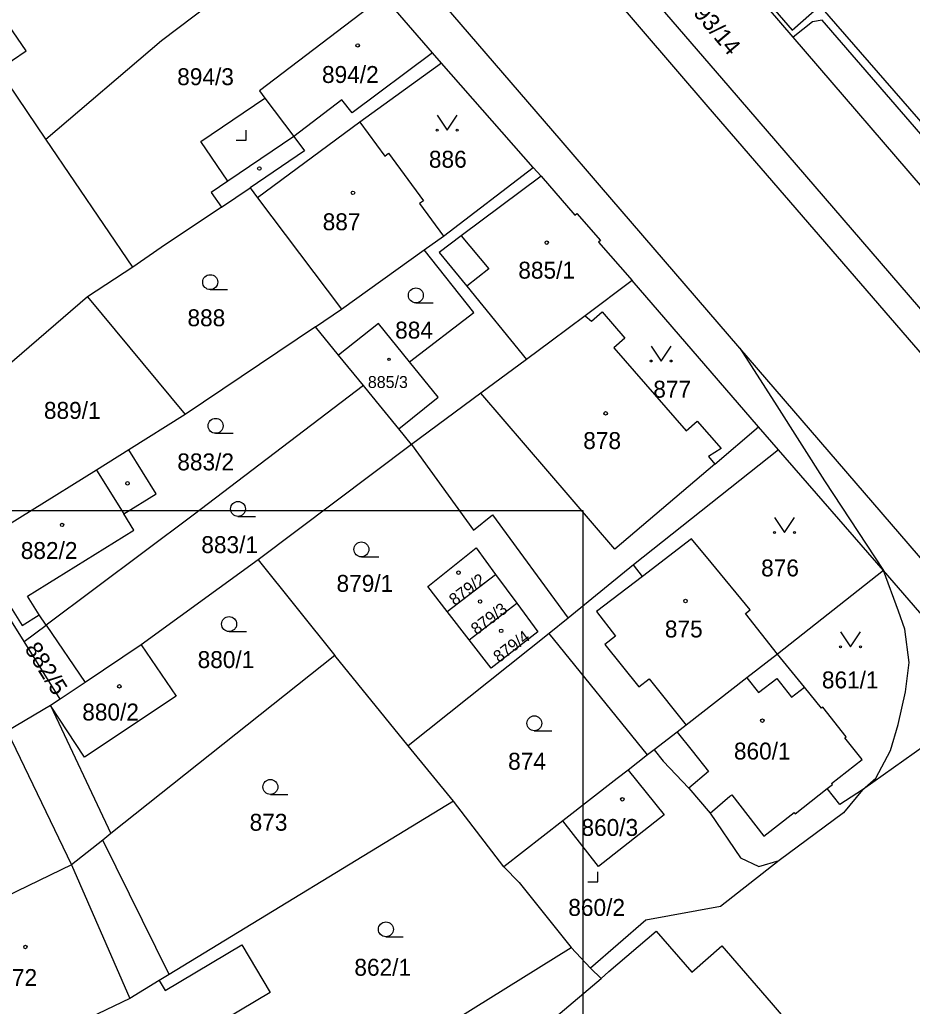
# Model space of a CAD drawing. Extents: x -496682 to -495776, y -1088797 to -1088018.
# Drawn here: x -496193.9 to -496104.3, y -1088214 to -1088115 of the extents above; entities that cross this region are included whole.
import ezdxf

# ---------------------------------------------------------------- set-up
doc = ezdxf.new("R2010")
doc.units = 0
for name, color, linetype in [('Hranice parcel', 7, 'Continuous'), ('Parcelní čísla', 7, 'Continuous'), ('Vnitřní kresba', 7, 'Continuous'), ('Vrstva 63', 7, 'Continuous'), ('Značky budov', 7, 'Continuous'), ('Značky kultur', 7, 'Continuous')]:
    doc.layers.add(name, color=color, linetype=linetype)

msp = doc.modelspace()

# ---------------------------------------------------------------- linework, layer by layer
at = {"layer": 'Hranice parcel'}
for p, q in [((-496152.45, -1088118.29), (-496157.35, -1088112.6)), ((-496075.55, -1088164.09), (-496116.26, -1088116.72)), ((-496151.53, -1088119.31), (-496152.45, -1088118.29)), ((-496142.34, -1088129.81), (-496151.53, -1088119.31)), ((-496182.51, -1088139.79), (-496191.24, -1088126.97)), ((-496151.33, -1088136.69), (-496142.34, -1088129.81)), ((-496153.28, -1088138.08), (-496151.33, -1088136.69)), ((-496161.59, -1088144.03), (-496153.28, -1088138.08)), ((-496182.51, -1088139.79), (-496187.08, -1088142.78)), ((-496132.39, -1088141.15), (-496137.12, -1088144.68)), ((-496119.71, -1088155.84), (-496132.39, -1088141.15)), ((-496187.08, -1088142.78), (-496198.32, -1088152.5)), ((-496187.08, -1088142.78), (-496177.27, -1088154.6)), ((-496164.19, -1088145.79), (-496161.59, -1088144.03)), ((-496164.19, -1088145.79), (-496177.27, -1088154.6)), ((-496161.87, -1088148.63), (-496164.19, -1088145.79)), ((-496159.38, -1088151.68), (-496161.87, -1088148.63)), ((-496177.27, -1088154.6), (-496182.92, -1088158.15)), ((-496154.55, -1088157.61), (-496155.82, -1088156.05)), ((-496117.71, -1088158.15), (-496119.71, -1088155.84)), ((-496154.55, -1088157.61), (-496169.94, -1088169.21)), ((-496117.71, -1088158.15), (-496132.27, -1088169.7)), ((-496107.18, -1088170.28), (-496117.71, -1088158.15)), ((-496169.94, -1088169.21), (-496181.67, -1088177.72)), ((-496169.94, -1088169.21), (-496162.24, -1088178.79)), ((-496107.18, -1088170.28), (-496117.81, -1088178.66)), ((-496096.21, -1088183.01), (-496107.18, -1088170.28)), ((-496150.97, -1088174.38), (-496146.11, -1088170.67)), ((-496146.11, -1088170.67), (-496143.99, -1088173.55)), ((-496148.77, -1088177.22), (-496150.97, -1088174.38)), ((-496148.77, -1088177.22), (-496143.99, -1088173.55)), ((-496138.84, -1088175.04), (-496140.75, -1088176.58)), ((-496193.41, -1088177.4), (-496191.21, -1088175.76)), ((-496191.21, -1088175.76), (-496187.29, -1088181.5)), ((-496189.82, -1088183.19), (-496193.41, -1088177.4)), ((-496140.75, -1088176.58), (-496154.9, -1088187.88)), ((-496130.86, -1088188.79), (-496140.75, -1088176.58)), ((-496181.67, -1088177.72), (-496187.29, -1088181.5)), ((-496162.24, -1088178.79), (-496184.73, -1088196.69)), ((-496154.9, -1088187.88), (-496162.24, -1088178.79)), ((-496187.29, -1088181.5), (-496189.82, -1088183.19)), ((-496189.82, -1088183.19), (-496190.77, -1088183.83)), ((-496096.21, -1088183.01), (-496109.3, -1088192.3)), ((-496190.77, -1088183.83), (-496195.13, -1088186.39)), ((-496190.77, -1088183.83), (-496184.73, -1088196.69)), ((-496150.33, -1088193.43), (-496154.9, -1088187.88)), ((-496130.21, -1088188.26), (-496130.86, -1088188.79)), ((-496130.86, -1088188.79), (-496132.79, -1088190.31)), ((-496150.33, -1088193.43), (-496178.87, -1088210.84)), ((-496145.28, -1088200.01), (-496150.33, -1088193.43)), ((-496139.35, -1088195.4), (-496145.28, -1088200.01)), ((-496184.73, -1088196.69), (-496185.54, -1088197.33)), ((-496178.87, -1088210.84), (-496185.54, -1088197.33)), ((-496162.6, -1088223.08), (-496138.52, -1088208.12)), ((-496138.52, -1088208.12), (-496136.58, -1088210.21)), ((-496178.87, -1088210.84), (-496179.86, -1088211.45)), ((-496136.58, -1088210.21), (-496135.52, -1088211.22))]:
    msp.add_line(p, q, dxfattribs=at)
for points in [[(-496121.59, -1088147.94), (-496135.68, -1088131.58), (-496139.54, -1088127.1), (-496152.9, -1088111.52), (-496154.28, -1088109.93), (-496192.25, -1088065.81), (-496197.08, -1088060.92), (-496210.28, -1088048.82), (-496224.09, -1088036.2), (-496238.46, -1088023.17), (-496242.493, -1088019.486)], [(-496181.151, -1088019.486), (-496180.97, -1088024.95), (-496179.9, -1088035.45), (-496177.55, -1088046.36), (-496174.16, -1088056.24), (-496169.6, -1088065.68), (-496164.16, -1088074.78), (-496158.66, -1088082.86), (-496152.68, -1088090.79), (-496145.28, -1088099.81), (-496124.8, -1088123.7), (-496085.88, -1088168.81)], [(-496116.26, -1088116.72), (-496137.09, -1088092.45), (-496144.2, -1088083.68), (-496150.73, -1088075.21), (-496154.49, -1088069.71), (-496160.82, -1088074.53), (-496156.15, -1088081.34), (-496150.43, -1088088.98), (-496143.13, -1088097.97), (-496122.6, -1088121.81), (-496081, -1088170.14)], [(-496129.35, -1088100.96), (-496116.34, -1088116.02), (-496113.57, -1088113.57)], [(-496191.24, -1088126.97), (-496179.64, -1088117.06), (-496163.37, -1088104.73)], [(-496157.35, -1088112.6), (-496169.82, -1088122.1), (-496169.28, -1088122.83), (-496166.37, -1088126.68)], [(-496113.57, -1088113.57), (-496085.45, -1088145.89), (-496086.2, -1088146.36)], [(-496191.24, -1088126.97), (-496196, -1088119.97), (-496193.23, -1088118.07), (-496195.38, -1088114.92)], [(-496086.2, -1088146.36), (-496113.33, -1088115), (-496114.3, -1088115.18), (-496116.26, -1088116.72)], [(-496152.45, -1088118.29), (-496160.5, -1088124.31), (-496161.54, -1088123.01), (-496166.37, -1088126.68)], [(-496151.53, -1088119.31), (-496159.75, -1088125.24), (-496157.24, -1088128.65), (-496156.86, -1088128.37), (-496153.36, -1088133.14), (-496153.74, -1088133.42), (-496151.33, -1088136.69)], [(-496166.37, -1088126.68), (-496172.98, -1088131.17), (-496174.67, -1088132.32), (-496173.63, -1088133.79)], [(-496142.34, -1088129.81), (-496141.55, -1088130.68), (-496138.15, -1088134.58), (-496137.97, -1088134.42), (-496135.59, -1088137.14), (-496135.77, -1088137.3), (-496132.39, -1088141.15)], [(-496173.63, -1088133.79), (-496170.75, -1088131.83), (-496169.99, -1088132.84), (-496161.59, -1088144.03)], [(-496173.63, -1088133.79), (-496179.66, -1088137.84), (-496182.51, -1088139.79)], [(-496154.75, -1088149.3), (-496148.28, -1088144.35), (-496153.28, -1088138.08)], [(-496137.12, -1088144.68), (-496140.55, -1088147.25), (-496143.01, -1088149.07), (-496147.58, -1088152.46), (-496154.55, -1088157.61)], [(-496137.12, -1088144.68), (-496136.49, -1088145.23), (-496135.4, -1088144.29), (-496133.14, -1088146.93), (-496134.25, -1088147.92), (-496127, -1088156.24), (-496125.87, -1088155.26), (-496123.48, -1088158.01), (-496124.75, -1088158.81), (-496124.12, -1088159.59), (-496119.71, -1088155.84)], [(-496154.75, -1088149.3), (-496157.87, -1088145.45), (-496161.87, -1088148.63)], [(-496036.91, -1088246.54), (-496039.16, -1088242.24), (-496043.62, -1088236.85), (-496051.67, -1088227.99), (-496069.06, -1088208.54), (-496096.57, -1088176.99), (-496121.59, -1088147.94)], [(-496121.59, -1088147.94), (-496117.88, -1088153.72), (-496113.1, -1088161.25), (-496107.18, -1088170.28)], [(-496155.82, -1088156.05), (-496151.87, -1088152.87), (-496154.75, -1088149.3)], [(-496159.38, -1088151.68), (-496176.46, -1088164.72), (-496191.21, -1088175.76)], [(-496155.82, -1088156.05), (-496158.8, -1088152.4), (-496159.38, -1088151.68)], [(-496154.55, -1088157.61), (-496148.33, -1088166.2), (-496146.42, -1088164.68), (-496138.84, -1088175.04)], [(-496182.92, -1088158.15), (-496186.17, -1088160.2), (-496199.12, -1088168.24)], [(-496191.21, -1088175.76), (-496191.91, -1088174.73), (-496193.08, -1088172.85), (-496182.41, -1088166.22), (-496183.43, -1088164.59), (-496180.18, -1088162.57), (-496182.92, -1088158.15)], [(-496117.81, -1088178.66), (-496121.03, -1088174.58), (-496120.57, -1088174.2), (-496124.47, -1088169.46), (-496126.44, -1088167.07), (-496131.38, -1088170.86), (-496132.27, -1088169.7)], [(-496193.41, -1088177.4), (-496195.37, -1088174.27), (-496199.12, -1088168.24)], [(-496150.97, -1088174.38), (-496152.91, -1088171.88), (-496148.07, -1088167.99), (-496146.11, -1088170.67)], [(-496132.27, -1088169.7), (-496134.8, -1088171.76), (-496138.84, -1088175.04)], [(-496109.3, -1088192.3), (-496107.94, -1088191.13), (-496106.49, -1088188.34), (-496105.71, -1088185.74), (-496104.98, -1088182.44), (-496104.61, -1088179.52), (-496105.03, -1088176.16), (-496105.67, -1088174.35), (-496107.18, -1088170.28)], [(-496143.99, -1088173.55), (-496141.88, -1088176.43), (-496146.57, -1088180.06), (-496148.77, -1088177.22)], [(-496181.67, -1088177.72), (-496178.17, -1088182.88), (-496187.37, -1088189), (-496190.77, -1088183.83)], [(-496117.81, -1088178.66), (-496120.89, -1088181.04), (-496126.99, -1088185.79), (-496127.9, -1088186.49), (-496130.21, -1088188.26)], [(-496109.3, -1088192.3), (-496111.56, -1088193.75), (-496112.82, -1088192.16), (-496112.3, -1088191.76), (-496112.4, -1088191.64), (-496109.33, -1088189.23), (-496111.05, -1088187.07), (-496110.92, -1088186.97), (-496113.28, -1088184), (-496113.41, -1088184.1), (-496115.11, -1088181.97), (-496117.81, -1088178.66)], [(-496130.21, -1088188.26), (-496129.29, -1088189.41), (-496126.73, -1088192.13), (-496124.59, -1088194.64), (-496121.54, -1088199.13), (-496119.68, -1088200), (-496117.65, -1088199.4)], [(-496132.79, -1088190.31), (-496129.18, -1088194.79), (-496135.77, -1088199.99), (-496139.35, -1088195.4)], [(-496132.79, -1088190.31), (-496133.9, -1088191.16), (-496139.35, -1088195.4)], [(-496109.3, -1088192.3), (-496111.2, -1088194.59), (-496117.65, -1088199.4)], [(-496185.54, -1088197.33), (-496188.66, -1088199.81), (-496204.1, -1088207.28)], [(-496145.28, -1088200.01), (-496143.73, -1088201.59), (-496138.52, -1088208.12)], [(-496117.65, -1088199.4), (-496123.55, -1088204), (-496131.03, -1088205.37), (-496136.58, -1088210.21)], [(-496135.52, -1088211.22), (-496134.74, -1088210.55), (-496130.01, -1088206.47), (-496126.43, -1088210.59), (-496123.42, -1088207.95), (-496118.45, -1088213.69), (-496114.82, -1088217.94), (-496115.42, -1088218.43), (-496112.79, -1088220.23), (-496111.62, -1088221.6), (-496111.79, -1088223.84), (-496113.66, -1088225.45)], [(-496179.86, -1088211.45), (-496179.28, -1088212.43), (-496171.58, -1088207.84), (-496168.73, -1088212.63), (-496176.42, -1088217.23), (-496169.35, -1088226.74)], [(-496179.86, -1088211.45), (-496182.82, -1088213.25), (-496186.02, -1088214.8), (-496198.35, -1088220.77)], [(-496140.48, -1088227.9), (-496138.4, -1088226.02), (-496144.6, -1088218.93), (-496135.52, -1088211.22)]]:
    msp.add_lwpolyline(points, dxfattribs=at)
at = {"layer": 'Vnitřní kresba'}
for p, q in [((-496175.69, -1088127.18), (-496169.28, -1088122.83)), ((-496159.75, -1088125.24), (-496169.99, -1088132.84)), ((-496166.37, -1088126.68), (-496165.28, -1088128.11)), ((-496172.98, -1088131.17), (-496175.69, -1088127.18)), ((-496165.28, -1088128.11), (-496170.75, -1088131.83)), ((-496141.55, -1088130.68), (-496149.57, -1088136.67)), ((-496149.57, -1088136.67), (-496151.77, -1088138.32)), ((-496149.57, -1088136.67), (-496146.8, -1088139.98)), ((-496151.77, -1088138.32), (-496148.99, -1088141.72)), ((-496146.8, -1088139.98), (-496148.99, -1088141.72)), ((-496148.99, -1088141.72), (-496143.01, -1088149.07)), ((-496134.15, -1088168.11), (-496147.58, -1088152.46)), ((-496124.12, -1088159.59), (-496134.15, -1088168.11)), ((-496186.17, -1088160.2), (-496183.43, -1088164.59)), ((-496131.38, -1088170.86), (-496135.99, -1088174.39)), ((-496194.78, -1088173.9), (-496193.61, -1088175.79)), ((-496135.99, -1088174.39), (-496134.09, -1088176.86)), ((-496193.61, -1088175.79), (-496191.91, -1088174.73)), ((-496134.09, -1088176.86), (-496135.16, -1088177.71)), ((-496135.16, -1088177.71), (-496131.72, -1088181.96)), ((-496131.72, -1088181.96), (-496130.69, -1088181.14)), ((-496130.69, -1088181.14), (-496126.99, -1088185.79)), ((-496120.89, -1088181.04), (-496119.72, -1088182.53)), ((-496119.72, -1088182.53), (-496117.89, -1088181.1)), ((-496117.89, -1088181.1), (-496116.41, -1088182.97)), ((-496116.41, -1088182.97), (-496115.11, -1088181.97)), ((-496195.13, -1088186.39), (-496188.66, -1088199.81)), ((-496127.9, -1088186.49), (-496126.37, -1088188.36)), ((-496126.37, -1088188.36), (-496124.76, -1088190.44)), ((-496124.76, -1088190.44), (-496126.73, -1088192.13)), ((-496116.06, -1088194.7), (-496112.82, -1088192.16)), ((-496124.59, -1088194.64), (-496122.61, -1088192.94)), ((-496122.61, -1088192.94), (-496122.41, -1088192.78)), ((-496122.41, -1088192.78), (-496119.19, -1088196.94)), ((-496119.19, -1088196.94), (-496116.16, -1088194.58)), ((-496116.16, -1088194.58), (-496116.06, -1088194.7)), ((-496188.66, -1088199.81), (-496182.82, -1088213.25))]:
    msp.add_line(p, q, dxfattribs=at)
at = {"layer": 'Vrstva 63'}
msp.add_lwpolyline([(-496137.346, -1088164.238), (-496137.346, -1088461.238), (-496557.346, -1088461.238), (-496557.346, -1088164.238)], close=True, dxfattribs=at)
at = {"layer": 'Značky budov'}
for centre, radius in [((-496159.947, -1088117.539), 0.175), ((-496169.817, -1088129.899), 0.175), ((-496160.427, -1088132.339), 0.175), ((-496140.977, -1088137.339), 0.175), ((-496156.795, -1088149.059), 0.117), ((-496135.067, -1088154.489), 0.175), ((-496183.047, -1088161.519), 0.175), ((-496189.617, -1088165.689), 0.175), ((-496149.827, -1088170.479), 0.175), ((-496147.667, -1088173.379), 0.175), ((-496127.057, -1088173.329), 0.175), ((-496145.547, -1088176.319), 0.175), ((-496183.867, -1088181.899), 0.175), ((-496119.337, -1088185.339), 0.175), ((-496133.397, -1088193.239), 0.175), ((-496193.297, -1088208.069), 0.175)]:
    msp.add_circle(centre, radius, dxfattribs=at)
at = {"layer": 'Značky kultur'}
for p, q in [((-496171.13, -1088127.05), (-496171.13, -1088126.05)), ((-496172.131, -1088127.05), (-496171.13, -1088127.05)), ((-496174.753, -1088142.06), (-496173.003, -1088142.06)), ((-496154.113, -1088143.39), (-496152.363, -1088143.39)), ((-496174.213, -1088156.49), (-496172.463, -1088156.49)), ((-496171.963, -1088164.83), (-496170.213, -1088164.83)), ((-496159.583, -1088168.9), (-496157.833, -1088168.9)), ((-496172.853, -1088176.4), (-496171.103, -1088176.4)), ((-496142.223, -1088186.36), (-496140.473, -1088186.36)), ((-496168.713, -1088192.75), (-496166.963, -1088192.75)), ((-496135.86, -1088201.53), (-496135.86, -1088200.53)), ((-496136.861, -1088201.53), (-496135.86, -1088201.53)), ((-496157.123, -1088207.05), (-496155.373, -1088207.05))]:
    msp.add_line(p, q, dxfattribs=at)
for points in [[(-496151.98, -1088124.559), (-496150.98, -1088126.06), (-496149.98, -1088124.559)], [(-496130.49, -1088147.729), (-496129.49, -1088149.23), (-496128.49, -1088147.729)], [(-496118.12, -1088164.939), (-496117.12, -1088166.44), (-496116.12, -1088164.939)], [(-496111.49, -1088176.429), (-496110.49, -1088177.93), (-496109.49, -1088176.429)]]:
    msp.add_lwpolyline(points, dxfattribs=at)
for centre, radius in [((-496151.98, -1088126.059), 0.1), ((-496149.98, -1088126.059), 0.1), ((-496174.753, -1088141.31), 0.75), ((-496154.113, -1088142.64), 0.75), ((-496130.49, -1088149.229), 0.1), ((-496128.49, -1088149.229), 0.1), ((-496174.213, -1088155.74), 0.75), ((-496171.963, -1088164.08), 0.75), ((-496118.12, -1088166.439), 0.1), ((-496116.12, -1088166.439), 0.1), ((-496159.583, -1088168.15), 0.75), ((-496172.853, -1088175.65), 0.75), ((-496111.49, -1088177.929), 0.1), ((-496109.49, -1088177.929), 0.1), ((-496142.223, -1088185.61), 0.75), ((-496168.713, -1088192), 0.75), ((-496157.123, -1088206.3), 0.75)]:
    msp.add_circle(centre, radius, dxfattribs=at)

# ---------------------------------------------------------------- texts
at = {"layer": 'Parcelní čísla'}
for s, height, rotation, p in [('2893/14', 1.7, 310, (-496127.968, -1088112.376)), ('879/2', 1.2, 37, (-496150.212, -1088173.847)), ('879/3', 1.2, 37, (-496148.022, -1088176.787)), ('879/4', 1.2, 37, (-496145.772, -1088179.567)), ('882/5', 1.7, 302, (-496193.43, -1088178.128))]:
    msp.add_text(s, height=height, rotation=rotation, dxfattribs=at).set_placement(p)
for s, height, p in [('894/3', 1.7, (-496178.063, -1088121.53)), ('894/2', 1.7, (-496163.533, -1088121.31)), ('886', 1.7, (-496152.804, -1088129.82)), ('887', 1.7, (-496163.464, -1088136.1)), ('885/1', 1.7, (-496143.83, -1088140.96)), ('888', 1.7, (-496177.034, -1088145.74)), ('884', 1.7, (-496156.19, -1088146.98)), ('885/3', 1.2, (-496158.93, -1088151.94)), ('877', 1.7, (-496130.284, -1088152.91)), ('889/1', 1.7, (-496191.44, -1088155.04)), ('878', 1.7, (-496137.314, -1088158.07)), ('883/2', 1.7, (-496178.053, -1088160.21)), ('882/2', 1.7, (-496193.763, -1088169.11)), ('883/1', 1.7, (-496175.643, -1088168.52)), ('876', 1.7, (-496119.464, -1088170.86)), ('879/1', 1.7, (-496162.073, -1088172.41)), ('875', 1.7, (-496129.124, -1088176.99)), ('880/1', 1.7, (-496176.013, -1088180.06)), ('861/1', 1.7, (-496113.363, -1088182.1)), ('880/2', 1.7, (-496187.593, -1088185.33)), ('860/1', 1.7, (-496122.193, -1088189.25)), ('874', 1.7, (-496144.854, -1088190.27)), ('873', 1.7, (-496170.794, -1088196.4)), ('860/3', 1.7, (-496137.493, -1088196.92)), ('860/2', 1.7, (-496138.813, -1088204.95)), ('862/1', 1.7, (-496160.283, -1088210.96)), ('872', 1.7, (-496195.914, -1088211.99))]:
    msp.add_text(s, height=height, dxfattribs=at).set_placement(p)

doc.saveas('drawing.dxf')
